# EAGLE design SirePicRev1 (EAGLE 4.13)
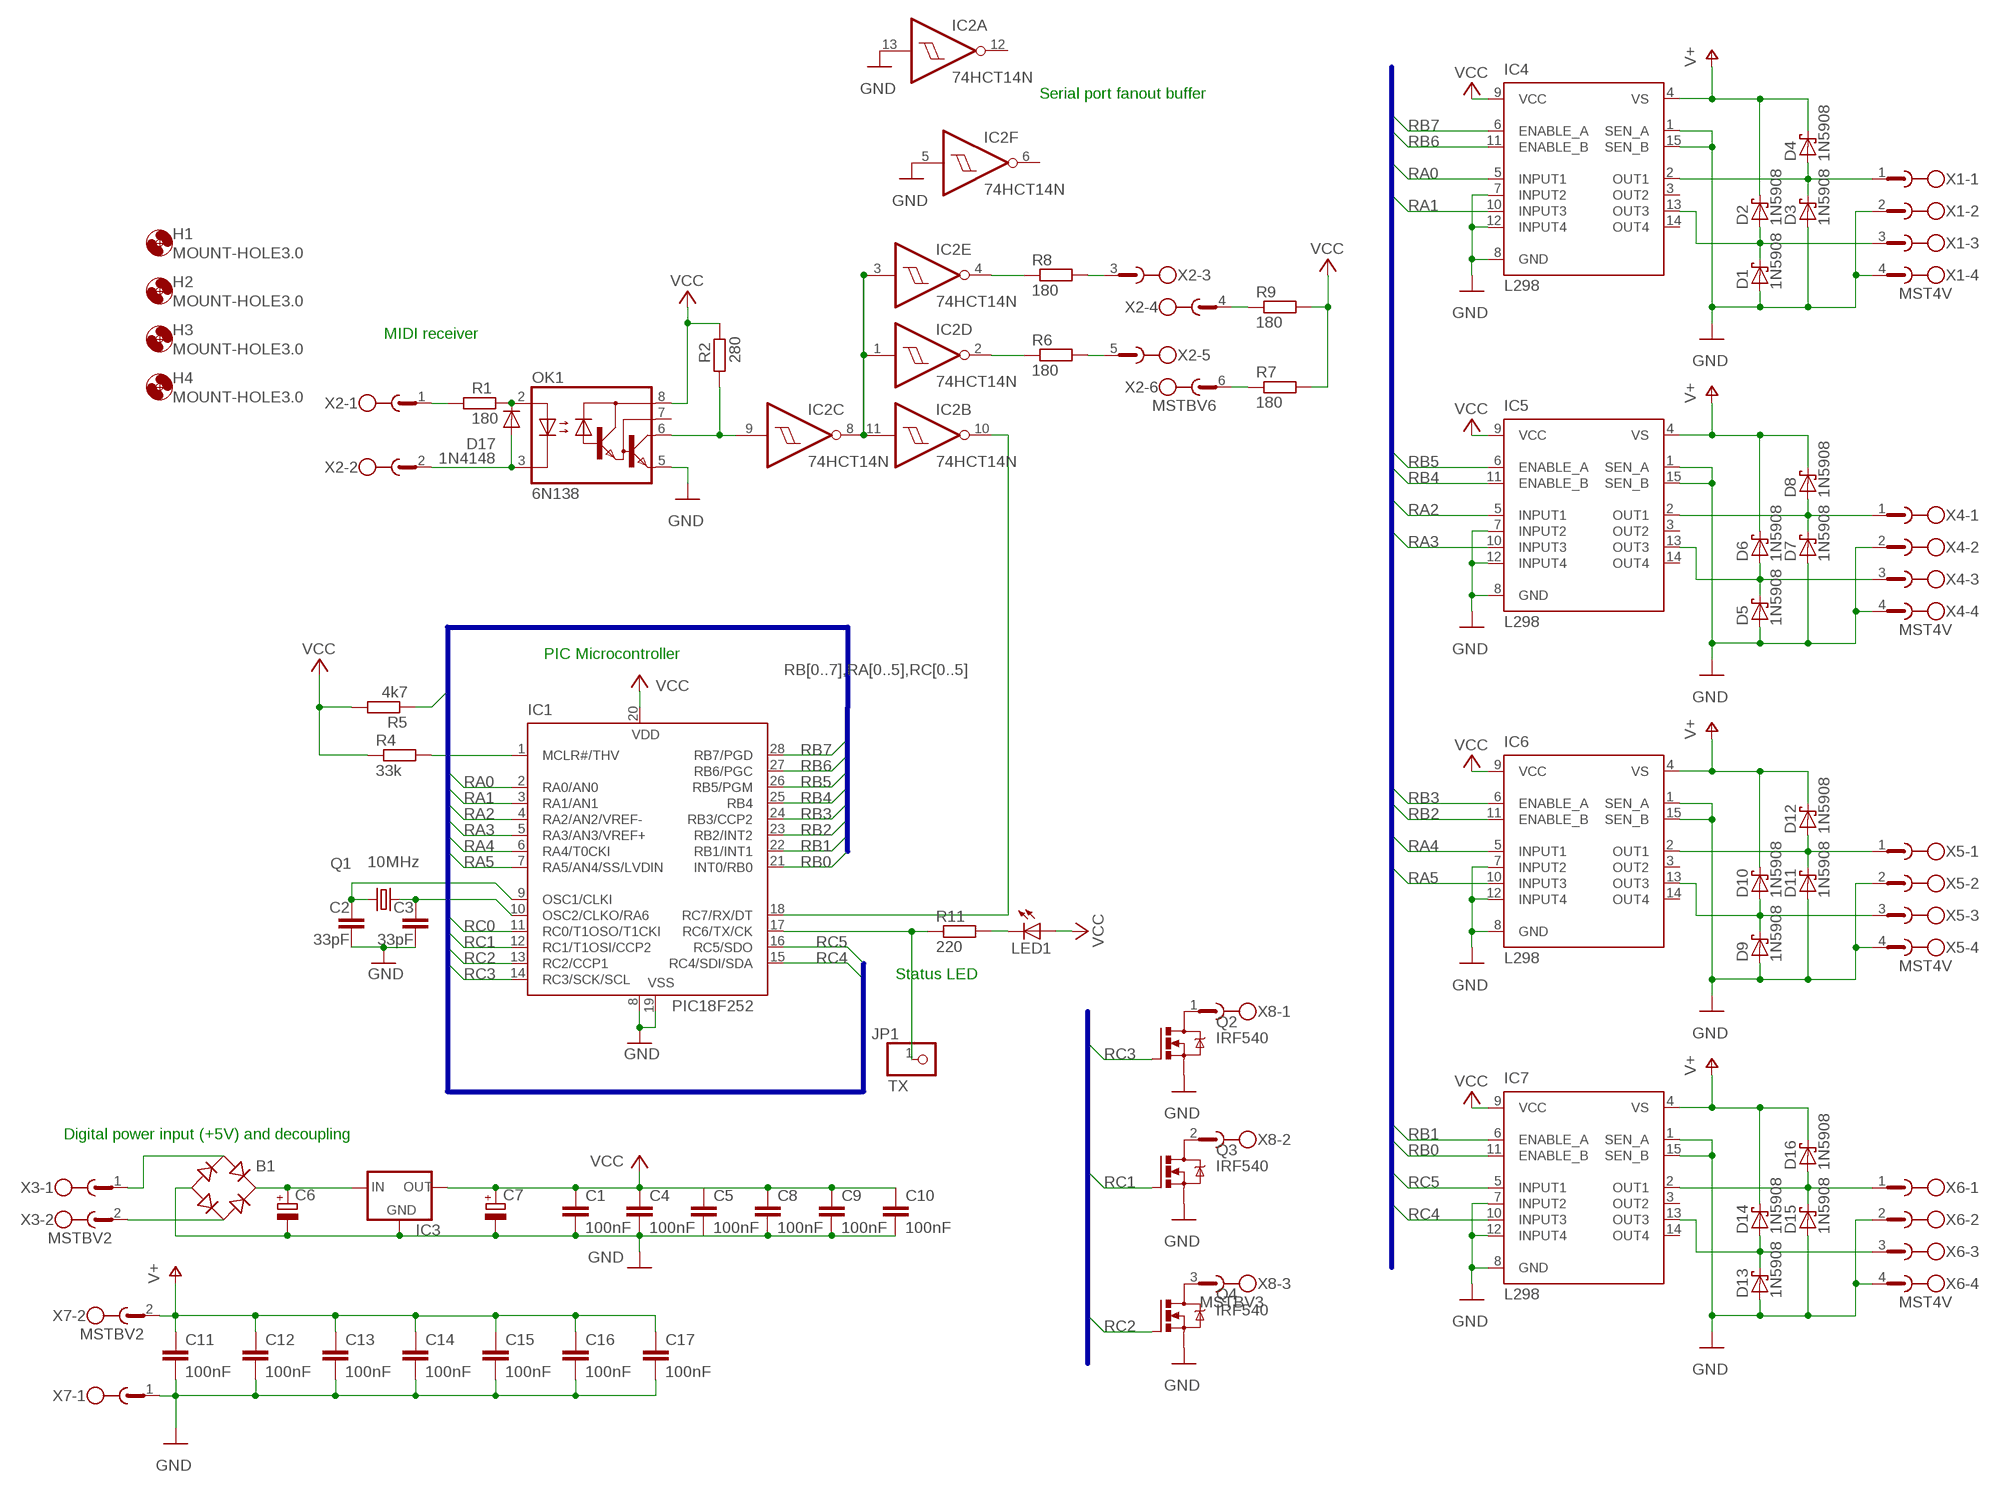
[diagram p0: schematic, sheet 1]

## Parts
B1  RB1A  [RB1A]
C1  100nF  C-EU025-025X050  [C025-025X050]
C2  33pF  C-EU025-025X050  [C025-025X050]
C3  33pF  C-EU025-025X050  [C025-025X050]
C4  100nF  C-EU025-025X050  [C025-025X050]
C5  100nF  C-EU025-025X050  [C025-025X050]
C6  CPOL-EUE5-10.5  [E5-10,5]
C7  CPOL-EUE5-10.5  [E5-10,5]
C8  100nF  C-EU025-025X050  [C025-025X050]
C9  100nF  C-EU025-025X050  [C025-025X050]
C10  100nF  C-EU025-025X050  [C025-025X050]
C11  100nF  C-EU025-025X050  [C025-025X050]
C12  100nF  C-EU025-025X050  [C025-025X050]
C13  100nF  C-EU025-025X050  [C025-025X050]
C14  100nF  C-EU025-025X050  [C025-025X050]
C15  100nF  C-EU025-025X050  [C025-025X050]
C16  100nF  C-EU025-025X050  [C025-025X050]
C17  100nF  C-EU025-025X050  [C025-025X050]
D1  1N5908  [C4111-15]
D2  1N5908  [C4111-15]
D3  1N5908  [C4111-15]
D4  1N5908  [C4111-15]
D5  1N5908  [C4111-15]
D6  1N5908  [C4111-15]
D7  1N5908  [C4111-15]
D8  1N5908  [C4111-15]
D9  1N5908  [C4111-15]
D10  1N5908  [C4111-15]
D11  1N5908  [C4111-15]
D12  1N5908  [C4111-15]
D13  1N5908  [C4111-15]
D14  1N5908  [C4111-15]
D15  1N5908  [C4111-15]
D16  1N5908  [C4111-15]
D17  1N4148  [DO35-10]
H1  MOUNT-HOLE3.0  [3,0]
H2  MOUNT-HOLE3.0  [3,0]
H3  MOUNT-HOLE3.0  [3,0]
H4  MOUNT-HOLE3.0  [3,0]
IC1  PIC18F252  [DIL28-3]
IC2  74HCT14N  [DIL14]
IC3  78XXS  [78XXS]
IC4  L298  [MULTIWATT-15]
IC5  L298  [MULTIWATT-15]
IC6  L298  [MULTIWATT-15]
IC7  L298  [MULTIWATT-15]
JP1  TX  PINHD-1X1  [1X01]
LED1  LED3MM  [LED3MM]
OK1  6N138  [DIL08]
Q1  10MHz  HC49U70  [HC49U70]
Q2  IRF540  [TO220BV]
Q3  IRF540  [TO220BV]
Q4  IRF540  [TO220BV]
R1  180  R-EU_0204/7  [0204/7]
R2  280  R-EU_0204/7  [0204/7]
R4  33k  R-EU_0204/7  [0204/7]
R5  4k7  R-EU_0204/7  [0204/7]
R6  180  R-EU_0204/7  [0204/7]
R7  180  R-EU_0204/7  [0204/7]
R8  180  R-EU_0204/7  [0204/7]
R9  180  R-EU_0204/7  [0204/7]
R11  220  R-EU_0204/7  [0204/7]
X1  MST4V  [MSTBV4]
X2  MSTBV6  [MSTBV6]
X3  MSTBV2  [MSTBV2]
X4  MST4V  [MSTBV4]
X5  MST4V  [MSTBV4]
X6  MST4V  [MSTBV4]
X7  MSTBV2  [MSTBV2]
X8  MSTBV3  [MSTBV3]

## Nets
GND: B1.- C1.2 C2.2 C3.2 C4.2 C5.2 C6.- C7.- C8.2 C9.2 C10.2 C11.2 C12.2 C13.2 C14.2 C15.2 C16.2 C17.2 D1.A D3.A D5.A D7.A D9.A D11.A D13.A D15.A IC1.8(VSS) IC1.19(VSS) IC2.5(F:I) IC2.13(A:I) IC3.GND IC4.1(SEN_A) IC4.7(INPUT2) IC4.8(GND) IC4.12(INPUT4) IC4.15(SEN_B) IC5.1(SEN_A) IC5.7(INPUT2) IC5.8(GND) IC5.12(INPUT4) IC5.15(SEN_B) IC6.1(SEN_A) IC6.7(INPUT2) IC6.8(GND) IC6.12(INPUT4) IC6.15(SEN_B) IC7.1(SEN_A) IC7.7(INPUT2) IC7.8(GND) IC7.12(INPUT4) IC7.15(SEN_B) OK1.5(GND) Q2.S Q3.S Q4.S X1.2 X1.4 X4.2 X4.4 X5.2 X5.4 X6.2 X6.4 X7.1
N$1: D17.C OK1.2(A) R1.2
N$2: R1.1 X2.1
N$3: C2.1 IC1.9(OSC1/CLKI) Q1.1
N$4: C3.1 IC1.10(OSC2/CLKO/RA6) Q1.2
N$5: D17.A OK1.3(C) X2.2
N$6: D7.C D8.A IC5.2(OUT1) X4.1
N$7: IC1.1(MCLR#/THV) R4.2
N$8: IC2.1(D:I) IC2.3(E:I) IC2.8(C:O) IC2.11(B:I)
N$9: IC2.9(C:I) OK1.6(VO) R2.1
N$10: R6.2 X2.5
N$11: IC1.17(RC6/TX/CK) JP1.1 R11.1
N$13: R7.1 X2.6
N$14: R8.2 X2.3
N$15: R9.1 X2.4
N$16: D5.C D6.A IC5.13(OUT3) X4.3
N$17: IC2.2(D:O) R6.1
N$18: IC2.4(E:O) R8.1
N$19: D11.C D12.A IC6.2(OUT1) X5.1
N$20: D3.C D4.A IC4.2(OUT1) X1.1
N$21: LED1.K(C) R11.2
N$22: B1.+ C6.+ IC3.IN
N$23: B1.AC2 X3.2
N$24: B1.AC1 X3.1
N$25: D1.C D2.A IC4.13(OUT3) X1.3
N$26: D9.C D10.A IC6.13(OUT3) X5.3
N$27: D15.C D16.A IC7.2(OUT1) X6.1
N$28: D13.C D14.A IC7.13(OUT3) X6.3
N$29: Q2.D X8.1
N$30: Q3.D X8.2
N$31: Q4.D X8.3
N$62: IC1.18(RC7/RX/DT) IC2.10(B:O)
RA0: IC1.2(RA0/AN0) IC4.5(INPUT1)
RA1: IC1.3(RA1/AN1) IC4.10(INPUT3)
RA2: IC1.4(RA2/AN2/VREF-) IC5.5(INPUT1)
RA3: IC1.5(RA3/AN3/VREF+) IC5.10(INPUT3)
RA4: IC1.6(RA4/T0CKI) IC6.5(INPUT1) R5.1
RA5: IC1.7(RA5/AN4/SS/LVDIN) IC6.10(INPUT3)
RB0: IC1.21(INT0/RB0) IC7.11(ENABLE_B)
RB1: IC1.22(RB1/INT1) IC7.6(ENABLE_A)
RB2: IC1.23(RB2/INT2) IC6.11(ENABLE_B)
RB3: IC1.24(RB3/CCP2) IC6.6(ENABLE_A)
RB4: IC1.25(RB4) IC5.11(ENABLE_B)
RB5: IC1.26(RB5/PGM) IC5.6(ENABLE_A)
RB6: IC1.27(RB6/PGC) IC4.11(ENABLE_B)
RB7: IC1.28(RB7/PGD) IC4.6(ENABLE_A)
RC0: IC1.11(RC0/T1OSO/T1CKI)
RC1: IC1.12(RC1/T1OSI/CCP2) Q3.G
RC2: IC1.13(RC2/CCP1) Q4.G
RC3: IC1.14(RC3/SCK/SCL) Q2.G
RC4: IC1.15(RC4/SDI/SDA) IC7.10(INPUT3)
RC5: IC1.16(RC5/SDO) IC7.5(INPUT1)
V+: C11.1 C12.1 C13.1 C14.1 C15.1 C16.1 C17.1 D2.C D4.C D6.C D8.C D10.C D12.C D14.C D16.C IC4.4(VS) IC5.4(VS) IC6.4(VS) IC7.4(VS) X7.2
VCC: C1.1 C4.1 C5.1 C7.+ C8.1 C9.1 C10.1 IC1.20(VDD) IC3.OUT IC4.9(VCC) IC5.9(VCC) IC6.9(VCC) IC7.9(VCC) LED1.A OK1.8(VCC) R2.2 R4.1 R5.2 R7.2 R9.2
Unconnected: IC2.6(F:O) IC2.12(A:O) IC4.3(OUT2) IC4.14(OUT4) IC5.3(OUT2) IC5.14(OUT4) IC6.3(OUT2) IC6.14(OUT4) IC7.3(OUT2) IC7.14(OUT4) OK1.7(VB)

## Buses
RB[0..7],RA[0..5],RC[0..5]
RA[0..5],RC[0..5]

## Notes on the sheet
- Serial port fanout buffer
- MIDI receiver
- PIC Microcontroller
- Status LED
- Digital power input (+5V) and decoupling

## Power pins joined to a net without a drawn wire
GND: IC2.7(P:GND)
VCC: IC2.14(P:VCC)

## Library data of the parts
B1 = rectifier:RB1A: RECTIFIER 1 A
C1-C5 C8-C17 = rcl:C-EU: CAPACITOR, European symbol
C6 C7 = rcl:CPOL-EU: POLARIZED CAPACITOR, European symbol
D1-D16 = diode:1N5908: DIODE
D17 = diode:1N4148: DIODE
H1-H4 = holes:MOUNT-HOLE: MOUNTING HOLE with drill center marker
IC1 = microchip:PIC18F252
IC2 = 74xx-eu:74*14: Hex schmitt trigger INVERTER
IC3 = v-reg:78XXS: VOLTAGE REGULATOR
IC4-IC7 = st-microelectronics:L298: DUAL FULL-BRIDGE DRIVER
JP1 = pinhead:PINHD-1X1: PIN HEADER
LED1 = led:LED: LED
OK1 = optocoupler:6N138: MOTOROLA OPTO COUPLER
Q1 = crystal:HC49U70: CRYSTAL
Q2-Q4 = transistor-power:IRF540: HEXFET Power MOSFET
R1 R2 R4-R9 R11 = rcl:R-EU_: RESISTOR, European symbol
X1 X4-X6 = con-phoenix-508:MST4V: PHOENIX
X2 = con-phoenix-508:MSTBV6: PHOENIX
X3 X7 = con-phoenix-508:MSTBV2: PHOENIX
X8 = con-phoenix-508:MSTBV3: PHOENIX

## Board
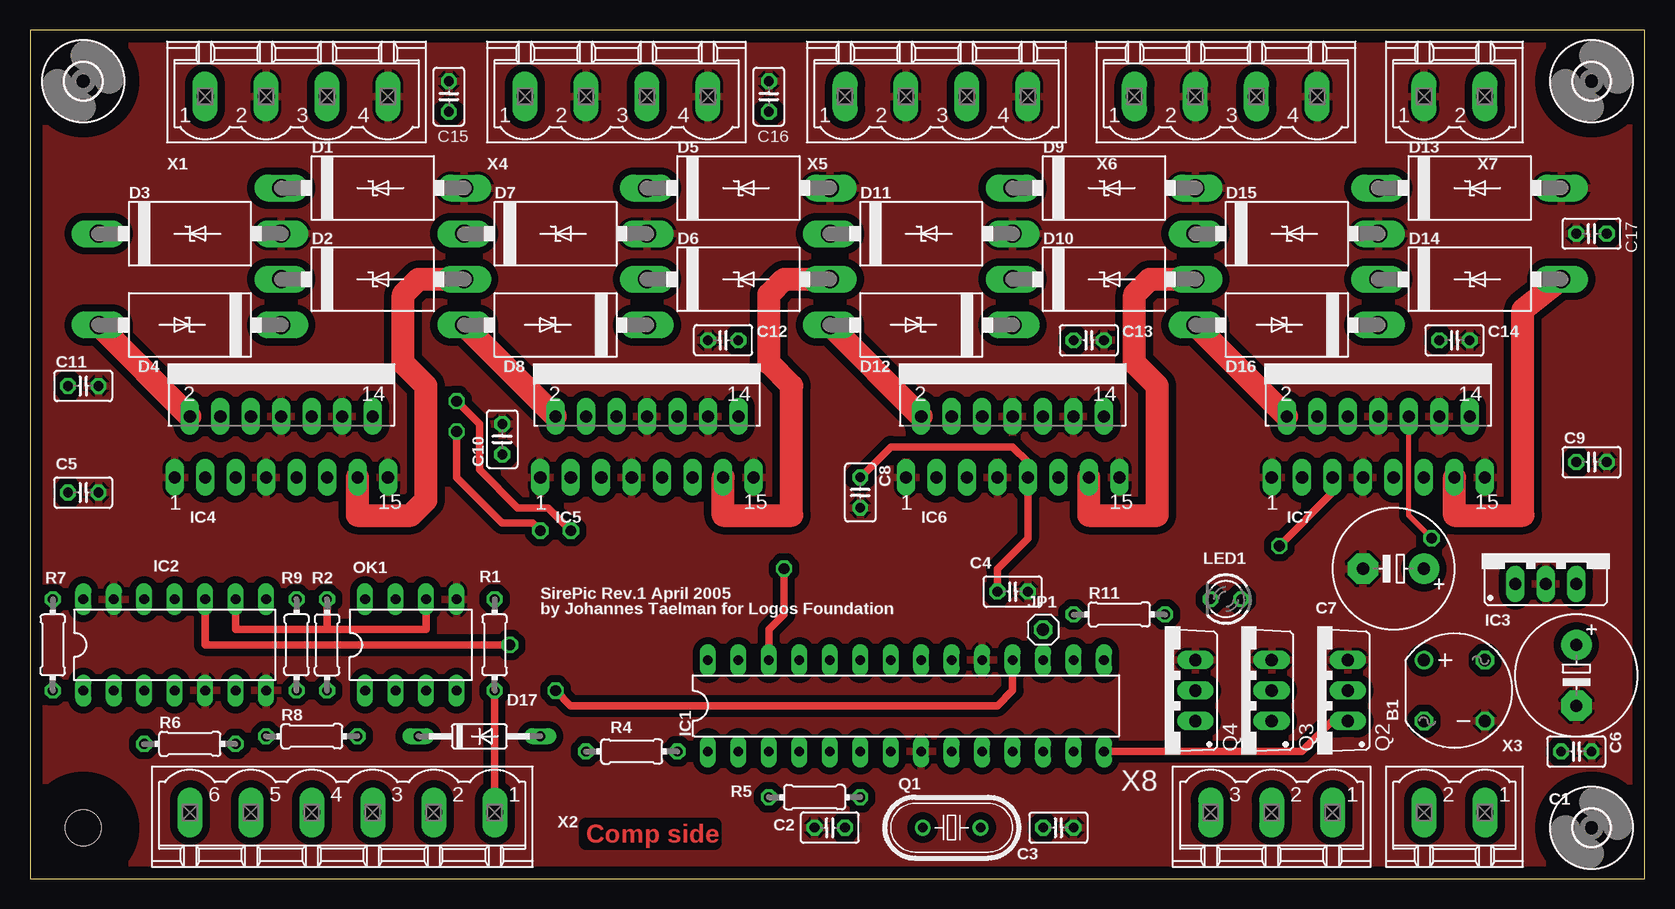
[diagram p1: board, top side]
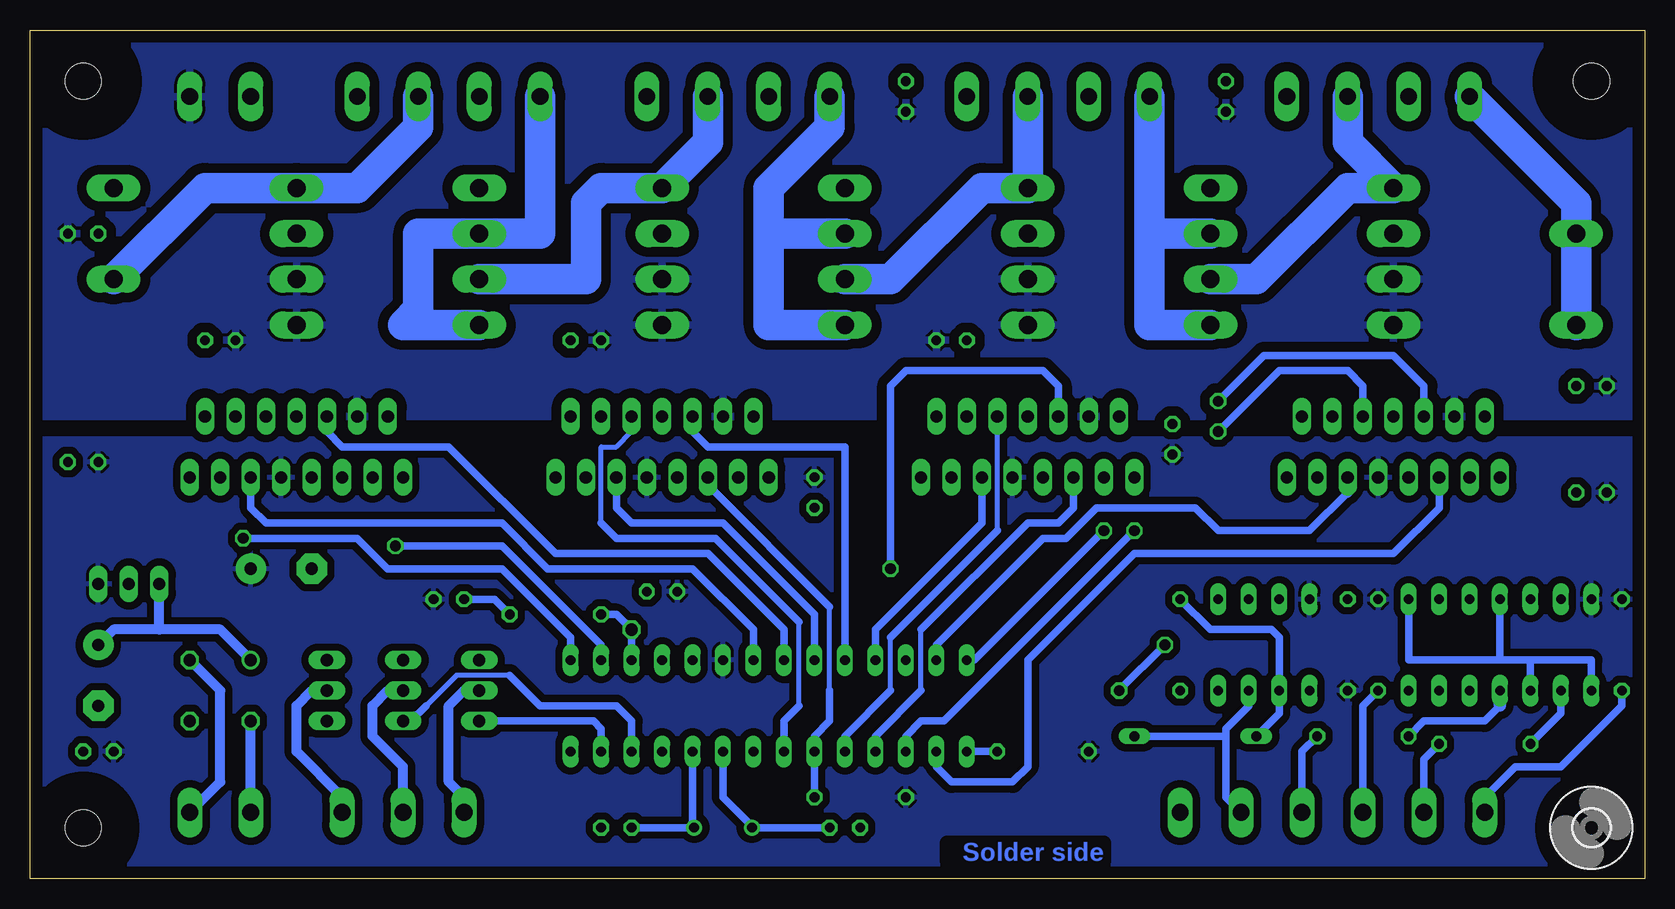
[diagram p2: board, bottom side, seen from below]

Size 134.6 x 70.79 mm. Coordinates in mm from the lower left corner, seen from the top.
Outline: 0,0 134.6,0 134.6,70.79 0,70.79 0,0
Copper layers (1*16): Top 0.035mm / dielectric 1.5mm / Bottom 0.035mm
Design rules "default": minimum track width 10mil, minimum drill 24mil, track to track 8mil, track to pad 8mil, pad to pad 8mil, via to via 8mil, smd to smd 8mil, copper to edge 40mil, drill to drill 8mil, minimum pad ring 10mil, minimum via ring 8mil, stop-mask expansion 0mil, vias tented up to drill 0mil, thermal gap 10mil

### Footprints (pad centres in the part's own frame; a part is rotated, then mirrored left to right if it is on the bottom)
RB1A = drill 1.016 round: + -2.54,2.54 | drill 1.016 octagon: - 2.54,-2.54; AC1 2.54,2.54; AC2 -2.54,-2.54
C025-025X050 = drill 0.813 octagon: 1 -1.27,0; 2 1.27,0
E5-10,5 = drill 1.016 pad 2.54 round: + -2.54,0 | drill 1.016 pad 2.54 octagon: - 2.54,0
C4111-15 = drill 1.499 long: A 7.62,0; C -7.62,0
DO35-10 = drill 0.813 long: A 5.08,0; C -5.08,0
3,0 = hole 3: 0,0
DIL28-3 = drill 0.813 long: 1 -16.51,-3.81; 2 -13.97,-3.81; 3 -11.43,-3.81; 4 -8.89,-3.81; 5 -6.35,-3.81; 6 -3.81,-3.81; 7 -1.27,-3.81; 8 1.27,-3.81; 9 3.81,-3.81; 10 6.35,-3.81; 11 8.89,-3.81; 12 11.43,-3.81; 13 13.97,-3.81; 14 16.51,-3.81; 15 16.51,3.81; 16 13.97,3.81; 17 11.43,3.81; 18 8.89,3.81; 19 6.35,3.81; 20 3.81,3.81; 21 1.27,3.81; 22 -1.27,3.81; 23 -3.81,3.81; 24 -6.35,3.81; 25 -8.89,3.81; 26 -11.43,3.81; 27 -13.97,3.81; 28 -16.51,3.81
DIL14 = drill 0.813 long: 1 -7.62,-3.81; 2 -5.08,-3.81; 3 -2.54,-3.81; 4 0,-3.81; 5 2.54,-3.81; 6 5.08,-3.81; 7 7.62,-3.81; 8 7.62,3.81; 9 5.08,3.81; 10 2.54,3.81; 11 0,3.81; 12 -2.54,3.81; 13 -5.08,3.81; 14 -7.62,3.81
78XXS = drill 1.016 long: GND 0,-2.54; IN -2.54,-2.54; OUT 2.54,-2.54
MULTIWATT-15 = drill 1.016 long: 1 -8.89,-7.62; 2 -7.62,-2.54; 3 -6.35,-7.62; 4 -5.08,-2.54; 5 -3.81,-7.62; 6 -2.54,-2.54; 7 -1.27,-7.62; 8 0,-2.54; 9 1.27,-7.62; 10 2.54,-2.54; 11 3.81,-7.62; 12 5.08,-2.54; 13 6.35,-7.62; 14 7.62,-2.54; 15 8.89,-7.62
1X01 = drill 1.016 octagon: 1 0,0
LED3MM = drill 0.813 octagon: A -1.27,0; K 1.27,0
DIL08 = drill 0.813 long: 1 -3.81,-3.81; 2 -1.27,-3.81; 3 1.27,-3.81; 4 3.81,-3.81; 5 3.81,3.81; 6 1.27,3.81; 7 -1.27,3.81; 8 -3.81,3.81
HC49U70@1 = drill 0.813 round: 1 -2.413,0; 2 2.413,0
TO220BV = drill 1.016 long: D 0,-2.54; G -2.54,-2.54; S 2.54,-2.54
0204/7 = drill 0.813 octagon: 1 -3.81,0; 2 3.81,0
MSTBV4 = drill 1.397 long: 1 -7.62,0; 2 -2.54,0; 3 2.54,0; 4 7.62,0
MSTBV6 = drill 1.397 long: 1 -12.7,0; 2 -7.62,0; 3 -2.54,0; 4 2.54,0; 5 7.62,0; 6 12.7,0
MSTBV2 = drill 1.397 long: 1 -2.54,0; 2 2.54,0
MSTBV3 = drill 1.397 long: 1 -5.08,0; 2 0,0; 3 5.08,0

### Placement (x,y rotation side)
B1  118.74,15.71 0 top
C1  128.9,10.63 0 top
C2  66.67,4.28 180 top
C3  85.72,4.28 0 top
C4  81.91,23.96 0 top
C5  4.44,32.22 0 top
C6  128.9,16.98 270 top
C7  113.66,25.87 180 top
C8  69.21,32.22 270 top
C9  130.17,34.76 0 top
C10  39.37,36.66 90 top
C11  4.44,41.11 0 top
C12  57.78,44.92 180 top
C13  88.26,44.92 0 top
C14  118.74,44.92 0 top
C15  34.92,65.24 90 top
C16  61.59,65.24 90 top
C17  130.17,53.81 180 top
D1  28.57,57.62 0 top
D2  28.57,50 0 top
D3  13.33,53.81 0 top
D4  13.33,46.19 180 top
D5  59.05,57.62 0 top
D6  59.05,50 0 top
D7  43.81,53.81 0 top
D8  43.81,46.19 180 top
D9  89.53,57.62 0 top
D10  89.53,50 0 top
D11  74.29,53.81 0 top
D12  74.29,46.19 180 top
D13  120.01,57.62 0 top
D14  120.01,50 0 top
D15  104.77,53.81 0 top
D16  104.77,46.19 180 top
D17  37.46,11.9 0 top
H1  4.44,4.28 0 bottom
H2  130.17,4.28 0 top
H3  130.17,66.51 0 top
H4  4.44,66.51 0 top
IC1  73.02,14.44 0 top
IC2  12.06,19.52 0 top
IC3  126.36,27.14 0 top
IC4  20.95,41.11 0 top
IC5  51.43,41.11 0 top
IC6  81.91,41.11 0 top
IC7  112.39,41.11 0 top
JP1  84.45,20.79 0 top
LED1  99.69,23.33 180 top
OK1  31.74,19.52 0 top
Q1  10MHz  [HC49U70@1]  76.83,4.28 0 top
Q2  107.31,15.71 90 top
Q3  100.96,15.71 90 top
Q4  94.61,15.71 90 top
R1  38.73,19.52 90 top
R2  24.76,19.52 270 top
R4  50.16,10.63 0 top
R5  65.4,6.82 180 top
R6  13.33,11.27 0 top
R7  1.9,19.52 90 top
R8  23.49,11.9 0 top
R9  22.22,19.52 90 top
R11  90.8,22.06 0 top
X1  22.22,65.24 0 top
X2  26.03,5.55 180 top
X3  118.74,5.55 180 top
X4  48.89,65.24 0 top
X5  75.56,65.24 0 top
X6  99.69,65.24 0 top
X7  118.74,65.24 0 top
X8  103.5,5.55 180 top

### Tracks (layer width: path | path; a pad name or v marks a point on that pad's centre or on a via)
GND
  pour Top (isolate 0.61): 0.63,70.32 133.98,70.32 133.98,0.47 0.63,0.47
N$1
  Bottom 0.61: D17.C 30.47,13.81 OK1.2 30.47,20.15 31.11,20.79 36.19,20.79 R1.2
N$2
  Top 0.61: X2.1 R1.1
N$3
  Bottom 0.61: 74.29,4.28 76.83,6.82 IC1.9 | 74.29,4.28 Q1.1 | C2.1 74.29,4.28
N$4
  Bottom 0.61: C3.1 Q1.2 79.37,4.15 IC1.10
N$5
  Bottom 0.61: X2.2 34.92,6.82 34.92,11.9 | 34.92,11.9 34.92,12.54 33.02,14.44 OK1.3 | 34.92,11.9 D17.A
N$6
  Top 1.93: D8.A IC5.2
  Bottom 2.54: 41.27,53.81 D7.C | 41.27,53.81 X4.1 | D8.A 41.27,46.19 41.27,53.81
N$7
  Bottom 0.61: R4.2 IC1.1
N$8
  Bottom 0.61: IC2.1 4.44,18.25 9.52,18.25 | 9.52,18.25 IC2.3 | 12.06,18.25 19.68,18.25 IC2.8 | 12.06,18.25 IC2.11 | 9.52,18.25 12.06,18.25
N$9
  Top 0.61: OK1.6 33.02,20.79 24.76,20.79 | 24.76,20.79 R2.1 | 24.76,20.79 17.14,20.79 IC2.9
N$10
  Bottom 0.61: R6.2 18.41,10 X2.5
N$11
  Bottom 0.61: IC1.17 JP1.1 85.72,22.06 R11.1
N$13
  Bottom 0.61: R7.1 1.9,14.44 6.98,9.36 10.79,9.36 13.33,6.82 X2.6
N$14
  Bottom 0.61: X2.3 28.57,10.63 R8.2
N$15
  Bottom 0.61: R9.1 23.49,14.44 X2.4
N$16
  Top 1.93: IC5.13 57.78,30.31 63.5,30.31 63.5,41.11 61.59,43.02 61.59,48.73 62.86,50 D6.A
  Bottom 2.54: X4.3 D5.C 55.24,57.62 62.86,50 D6.A
N$17
  Bottom 0.61: R6.1 6.98,13.81 IC2.2
N$18
  Bottom 0.61: R8.1 18.41,13.17 13.33,13.17 12.06,14.44
  Bottom 1.016: 12.06,14.44 IC2.4
N$19
  Top 1.93: D12.A IC6.2
  Bottom 2.54: D12.A 73.02,46.19 73.02,53.81 | 73.02,53.81 D11.C | X5.1 67.94,62.7 73.02,57.62 73.02,53.81
N$20
  Top 1.93: D4.A IC4.2
  Bottom 2.54: X1.1 5.71,56.35 D3.C D4.A
N$21
  Bottom 0.61: R11.2 95.88,23.33 LED1.K
N$22
  Bottom 0.813: 123.82,20.79 127.63,20.79 C6.+ | B1.+ 118.74,20.79 123.82,20.79 | 123.82,20.79 IC3.IN
N$23
  Bottom 0.813: X3.2 B1.AC2
N$24
  Bottom 0.813: X3.1 118.74,8.09 118.74,15.71 B1.AC1
N$25
  Top 1.93: IC4.13 27.3,30.31 31.74,30.31 33.02,31.58 33.02,41.11 31.11,43.02 31.11,48.73 32.38,50 D2.A
  Bottom 2.54: X1.3 24.76,61.43 D1.C 24.76,57.62 32.38,50 D2.A
N$26
  Top 1.93: IC6.13 88.26,30.31 93.97,30.31 93.97,41.11 92.07,43.02 92.07,48.73 93.34,50 D10.A
  Bottom 2.54: X5.3 78.1,61.43 D9.C 86.99,57.62 88.26,56.35 88.26,50 D10.A
N$27
  Top 1.93: D16.A IC7.2
  Bottom 2.54: D16.A 103.5,46.19 102.23,47.46 102.23,53.81 D15.C 92.07,53.81 X6.1
N$28
  Top 1.93: IC7.13 118.74,30.31 124.45,30.31 124.45,47.46 D14.A
  Bottom 2.54: X6.3 102.23,62.7 107.31,57.62 D13.C 120.01,57.62 D14.A
N$29
  Bottom 0.813: Q2.D 111.12,15.71 112.39,14.44 112.39,10.63 108.58,6.82 X8.1
N$30
  Bottom 0.813: Q3.D 104.77,15.71 106.04,14.44 106.04,11.9 103.5,9.36 X8.2
N$31
  Bottom 0.813: Q4.D 98.42,15.71 99.69,14.44 99.69,8.09 98.42,6.82 X8.3
N$62  (via drill 0.9)
  Top 0.61: IC2.10 14.6,19.52 v40,19.52 | IC1.18 81.91,15.71 80.64,14.44 45.08,14.44 v43.81,15.71
  Bottom 0.61: v40,19.52 v43.81,15.71
RA0
  Bottom 0.61: IC4.5 17.14,30.95 20.95,27.14 42.54,27.14 51.43,18.25 51.43,9.36 52.7,8.09 57.78,8.09 59.05,9.36 IC1.2
RA1  (via drill 0.9)
  Top 0.61: v35.55,37.3 35.55,33.49 39.37,29.68 41.91,29.68 v42.54,29.04
  Bottom 0.61: IC4.10 23.49,41.11 24.76,42.38 30.47,42.38 v35.55,37.3 | v42.54,29.04 58.41,13.17 60.32,13.17 61.59,11.9 IC1.3
RA2
  Bottom 0.406: 60.32,15.71 60.32,20.79
  Bottom 0.61: IC1.4 64.13,11.9 60.32,15.71 | 60.32,20.79 51.43,29.68 48.89,29.68 47.62,30.95 IC5.5
RA3
  Bottom 0.406: 53.97,29.04 IC5.10 | 62.86,15.71 62.86,20.15
  Bottom 0.61: IC1.5 66.67,11.9 62.86,15.71 | 62.86,20.15 53.97,29.04
RA4
  Bottom 0.406: 67.94,15.71 67.94,22.7
  Bottom 0.61: 67.94,15.71 67.94,13.17 69.21,11.9 IC1.6 R5.1 | 67.94,22.7 78.1,32.85 IC6.5
RA5
  Bottom 0.406: 70.48,14.44 70.48,21.42 | 86.99,29.68 86.99,36.03 85.72,36.03 84.45,37.3 IC6.10
  Bottom 0.61: IC1.7 71.75,13.17 70.48,14.44 | 70.48,21.42 77.46,28.41 85.72,28.41 86.99,29.68
RB0
  Bottom 0.61: IC1.21 74.29,20.79 79.37,25.87 91.44,25.87 95.24,29.68 114.93,29.68 116.2,30.95 IC7.11
RB1
  Bottom 0.61: IC1.22 71.75,20.79 78.1,27.14 90.8,27.14 99.69,36.03 108.58,36.03 109.85,37.3 IC7.6
RB2
  Bottom 0.61: IC1.23 69.21,22.06 76.83,29.68 84.45,29.68 85.72,30.95 IC6.11
RB3
  Bottom 0.61: IC1.24 66.67,36.03 78.1,36.03 79.37,37.3 IC6.6
RB4
  Bottom 0.61: IC1.25 64.13,20.79 55.24,29.68 IC5.11
RB5  (via drill 0.9)
  Top 0.61: IC1.26 61.59,20.79 62.86,22.06 v62.86,25.87
  Bottom 0.61: v62.86,25.87 62.86,41.11 61.59,42.38 50.16,42.38 48.89,41.11 IC5.6
RB6
  Bottom 0.61: 24.76,32.22 27.93,29.04 35.55,29.04 37.46,30.95 45.72,30.95 48.26,28.41 50.16,28.41 59.05,19.52 IC1.27
  Bottom 0.813: 24.76,32.22 IC4.11
RB7  (via drill 0.9)
  Top 0.61: v35.55,39.84 37.46,37.94 37.46,34.12 40.64,30.95 43.18,30.95 v45.08,29.04
  Bottom 0.61: IC4.6 18.41,41.11 20.95,43.65 31.74,43.65 v35.55,39.84 | v45.08,29.04 55.88,18.25 IC1.28
RC1
  Bottom 0.406: 94.61,16.98 99.05,16.98 101.59,14.44
  Bottom 0.61: IC1.12 84.45,13.17 85.72,14.44 92.07,14.44 94.61,16.98 | 101.59,14.44 102.86,13.17 Q3.G
RC2
  Bottom 0.61: IC1.13 86.99,12.54 87.62,13.17 Q4.G
RC3
  Top 0.61: IC1.14 106.04,10.63 108.58,13.17 Q2.G
RC4  (via drill 0.9)
  Top 0.406: v116.83,28.41 114.93,30.31 IC7.10
  Bottom 0.61: IC1.15 89.53,20.15 95.24,25.87 104.77,25.87 107.31,28.41 v116.83,28.41
RC5  (via drill 0.9)
  Top 0.61: v104.13,27.77 108.58,32.22 IC7.5
  Bottom 0.61: IC1.16 86.99,19.52 95.24,27.77 v104.13,27.77
V+
  pour Bottom (isolate 0.813): 0.63,70.32 135.25,70.32 135.25,38.57 0.63,38.57
VCC
  Top 0.61: C4.1 80.64,25.87 83.18,28.41 IC6.9 83.18,34.76 81.91,36.03 71.75,36.03 C8.1
  pour Bottom (isolate 0.61): 0.63,36.66 133.98,36.66 133.98,0.47 0.63,0.47

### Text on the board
Top: Comp side
Bottom: Solder side
tNames: SirePic Rev.1 April 2005 | by Johannes Taelman for Logos Foundation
